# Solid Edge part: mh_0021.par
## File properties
Title: spring
Author: edge
Template: normal.par
Last saved by: edge
Revision: 33
Application: Solid Edge
Material: SWM-B
非切断部品: False
文書内容のタイプ: 0
Density: 0.007850 g/mm^3
Accuracy: 0.99
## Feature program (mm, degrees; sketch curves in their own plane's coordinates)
sketch for "unnamed Protrusion 1" plane through (0, 0, 0) normal (0, 0, 1) x-axis (1, 0, 0)
extrude "unnamed Protrusion 1" add finite 10 symmetric
thinwall "Thinwall_1"  Thickness = 1 mm
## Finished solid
Body 1: solid body, 4 faces, 4 edges, 0 vertices.
  Faces by surface: cylinder 2, plane 2
  Edges by curve: circle 4
Bounding box of the edges (mm): 10.000 x 10.000 x 10.000, from (-5, -5, -5) to (5, 5, 5).
Cylindrical faces by radius (mm): R4 x1, R5 x1
Planar faces by outward normal: +z 1, -z 1
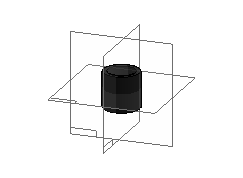
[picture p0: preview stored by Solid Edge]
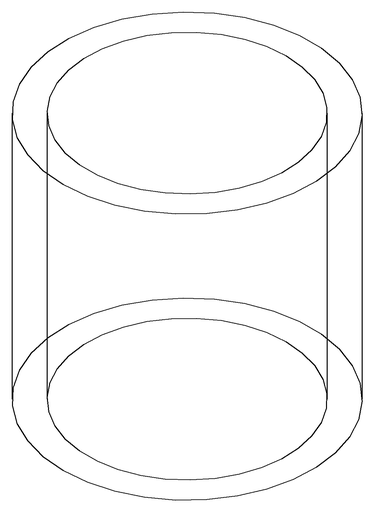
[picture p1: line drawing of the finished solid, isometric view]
